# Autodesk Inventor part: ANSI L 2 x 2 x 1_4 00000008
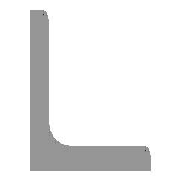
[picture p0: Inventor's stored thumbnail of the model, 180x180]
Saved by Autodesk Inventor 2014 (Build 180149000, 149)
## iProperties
IsCustomPart: 1
Created: 2007-02
Part Number: ANSI L 2 x 2 x 1_4 00000008
Material: Steel, Mild
Document SubType Name: Modeling
Standard: AISC
Designer: Autodesk, Inc.
Size Designation: L 2 x 2 x 1/4
Stock Number: L 2 x 2 x 1/4
Density: 7.86 g/cm^3
Description: Angle Steel
Standards Organization: ANSI
Language: en-US
Categories: <MemberInstance><Categories><Category DisplayName="Structural Shapes" InternalName="089c4875-fa83-4c05-b084-43b9cc11f5ed" Mnemonic="GRDR"><CategoryParameter Dis
Mass: 3370.02 g
Surface Area: 1403.81 cm^2
Volume: 428.755 cm^3
Appearance: Steel
_FrameMemberDoc: Frame Member File
_Version: 15.0.0
_CCFamilyMember: 11
_CCFamilyDisplayName: ANSI L (Equal angles) - Angle Steel
G_L: 28.000 in
G_W: 2.000 in
G_H: 2.000 in
+10DDB0D1-7D7B-4E40-902A-8651B9802CE2+CUTDETAIL1: Notch
+0608949D-539C-4EC4-9C9E-4114D78E7297+CUTDETAIL2: Notch
Author: Autodesk, Inc.
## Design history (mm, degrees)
node "Start plane"
node "End plane"
sketch "Sketch"
  geometry: L1 (50.8, 0)-(0, 0); L2 (0, 0)-(0, 50.8); L3 (0, 50.8)-(3.302, 50.8); L4 (6.35, 47.752)-(6.35, 12.7); L5 (12.7, 6.35)-(47.752, 6.35); L6 (50.8, 3.302)-(50.8, 0); L7 (0, -11.041)-(0, 31.538); L8 (-11.041, 0)-(31.538, 0); L9 (0, 63.926)-(0, -23.536) reference; L10 (-23.536, 0)-(63.926, 0) reference; A1 r 6.35 centre (12.7, 12.7) between (6.35, 12.7) and (12.7, 6.35); A2 r 3.048 centre (3.302, 47.752) between (6.35, 47.752) and (3.302, 50.8); A3 r 3.048 centre (47.752, 3.302) between (50.8, 3.302) and (47.752, 6.35); 3 further points
  constraints: 16 end point, 6 point on circle, 6 point on line, 6 tangent, 4 parallel, 3 centre point, 2 collinear, 1 equal radius, 1 horizontal, 1 perpendicular
  dimensions: "d0" = 50.8 distance between parallel lines of L6 L2 (= G_H); "d1" = 50.8 distance between parallel lines of L3 L1 (= G_H); "d2" = 6.35 distance between parallel lines of L2 L4 (= G_T); "d3" = 6.35 distance between parallel lines of L1 L5 (= G_T); "d10" = 0 distance between parallel lines of L7 L2 (computed from ex); "d11" = 0 distance between parallel lines of L8 L1 (computed from d10); "d14" = 6.35 radius of A1 (= G_IR); "d15" = 3.048 radius of A2 (= G_ER)
extrude "Body" new body sketch "Sketch" stored distance "d4" = 711.2 (= G_L); taper "d5" = 0 deg
node "Driven Length"
  sketch "Sketch5"
    geometry: L1 (0, 0)-(10, 0) reference
    constraints: 2 end point, 1 horizontal
  workplane "Work Plane7"
  sketch "Sketch6"
    geometry: L1 (-2, 0)-(12, 0) reference; L2 (-2, 711.2)-(12, 711.2) reference
    dimensions: "d21" = 711.2 distance between parallel lines of L1 L2 (derived)
workplane "Work Plane3"
workplane "Work Plane4"
workplane "Work Plane5"
workplane "Work Plane6"
workplane "Work Plane8"
workplane "Work Plane9"
body "Solid1"
sketch "Sketch_1"
  geometry: L1 (50.8, 0)-(0, 0); L2 (0, 0)-(0, 50.8); L3 (0, 50.8)-(3.302, 50.8); L4 (6.35, 47.752)-(6.35, 12.7); L5 (12.7, 6.35)-(47.752, 6.35); L6 (50.8, 3.302)-(50.8, 0); A1 r 3.048 centre (3.302, 47.752) between (6.35, 47.752) and (3.302, 50.8); A2 r 6.35 centre (12.7, 12.7) between (6.35, 12.7) and (12.7, 6.35); A3 r 3.048 centre (47.752, 3.302) between (50.8, 3.302) and (47.752, 6.35)
  constraints: 12 end point, 6 point on circle, 3 centre point
extrude "Extrusion2" cut sketch "Sketch_1" stored distance "d22" = 3.302; taper "d23" = 0 deg
sketch "Sketch_2"
  geometry: L1 (50.8, 0)-(0, 0); L2 (0, 0)-(0, 50.8); L3 (0, 50.8)-(3.302, 50.8); L4 (6.35, 47.752)-(6.35, 12.7); L5 (12.7, 6.35)-(47.752, 6.35); L6 (50.8, 3.302)-(50.8, 0); A1 r 3.048 centre (3.302, 47.752) between (6.35, 47.752) and (3.302, 50.8); A2 r 6.35 centre (12.7, 12.7) between (6.35, 12.7) and (12.7, 6.35); A3 r 3.048 centre (47.752, 3.302) between (50.8, 3.302) and (47.752, 6.35)
  constraints: 12 end point, 6 point on circle, 3 centre point
extrude "Extrusion3" cut sketch "Sketch_2" stored distance "d24" = 3.302; taper "d25" = 0 deg
other parameters: "G_H" = 50.8 [user parameter; used in 2 equation terms], "G_T" = 6.35 [user parameter; used in 2 equation terms], "G_ER" = 3.048 [user parameter; used in 1 equation term], "G_IR" = 6.35 [user parameter; used in 1 equation term], "G_L" = 711.2 (= d21) [user parameter; used in 1 equation term], "ex" = 0 [user parameter; used in 1 equation term], "G_OFFSET_START" = 0 [user parameter; used in 1 equation term], "G_OFFSET_END" = 0 [user parameter; used in 1 equation term], "d12" = 0 (computed from G_OFFSET_START), "d13" = 711.2 (= G_OFFSET_END + B_L), "B_L" = 711.2 [user parameter; used in 1 equation term], "d20" = 90 deg
